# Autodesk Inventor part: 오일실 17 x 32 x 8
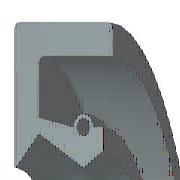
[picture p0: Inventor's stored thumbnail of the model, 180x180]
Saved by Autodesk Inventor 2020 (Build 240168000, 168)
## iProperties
IsCustomPart: 1
Created: 2012-02
Part Number: 오일실 17 x 32 x 8
Material: 고무
Description: 오일-실
Document SubType Name: Modeling
Standard: KS B 2804
Designer: mduedu
Standards Organization: KS
Language: ko-KR
Size Designation: D - 17 32 8
Categories: <MemberInstance><Categories><Category DisplayName="샤프트 부품" InternalName="7f7aeb1f-a693-4053-b835-cee3144e0d98" Mnemonic="SHFT"><Category DisplayName="실링" Intern
Density: 0.93 g/cm^3
Mass: 2.28027 g
Surface Area: 32.1224 cm^2
Volume: 2.45191 cm^3
Appearance: 고무 - 검은색 - 버전 1.1
Author: mduedu
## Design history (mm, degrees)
revolve "본체" stored, may be unused: angle "d17" = 90 deg
revolve "스프링1" stored, may be unused: angle "d18" = 90 deg
body "Solid1"
sketch "스케치1"
  geometry: L1 (0, 16)-(8, 16); L2 (8, 14.25)-(1.75, 14.25); L3 (1.75, 10.25)-(4.9, 8.5); L4 (4.9, 8.5)-(0, 8.5); L5 (0, 0)-(9.586, 0) reference; L6 (4.9, 8.5)-(6.3, 9.375); L7 (0, 18)-(0, -3) reference; L8 (-1.941, 0)-(11.507, 0) reference; L9 (4.2, 10.6)-(1.75, 11.21); L10 (1.75, 11.21)-(1.75, 14.25); L11 (0, 16)-(0, 8.588); L12 (4.9, 8.5)-(0, 8.5); L13 (1.75, 10.25)-(0.152, 8.528); L14 (8, 16)-(8, 14.25); L15 (5.6, 10.6)-(6.3, 10.6); L16 (6.3, 10.6)-(6.3, 9.375); C1 r 0.455 at (4.9, 10.6); A1 r 0.7 centre (4.9, 10.6) between (5.6, 10.6) and (4.2, 10.6); A2 r 0.088 centre (0.088, 8.588) between (0, 8.588) and (0.152, 8.528); 1 further point
  constraints: 28 end point, 5 horizontal alignment, 5 point on line, 4 point on circle, 4 vertical alignment, 3 centre point, 3 tangent, 2 collinear, 2 horizontal, 2 perpendicular, 1 coincident, 1 parallel
  dimensions: "d0" = 32 diameter of L1 L5 (= SD2); "d1" = 1.75 distance of L1.end L2.start (= SD); "d2" = 0.91 diameter of C1 (= SPDI); "d3" = 1.4 diameter of A1 (= SPDA); "d4" = 17 diameter of L3.end L5 (= NND); "d5" = 20.5 diameter of L3.start L5 (= TKDM); "d7" = 22.42 diameter of L9.end L5 (= TKDM + 0.24 x SWDT); "d8" = 1.75 distance between parallel lines of L11 L10 (= SD); "d9" = 4.9 distance from line of L11 C1.centre (= SPDST); "d10" = 21.2 diameter of C1.centre L5 (= HLDM); "d11" = 0.0875 radius of A2 (= 0.25 x LAB); "d12" = 6.3 distance between parallel lines of L11 L16 (= SDI); "d13" = 18.75 diameter of L6.end L5 (= ABDM); "d14" = 8 distance from line of L11 L1.end (= SWDT)
fillet "모깎기1" dims "d6" = 0.3 (= RR)
other parameters: "SD2" = 32 [user parameter; used in 1 equation term], "SWDT" = 8 [user parameter; used in 2 equation terms], "RR" = 0.3 [user parameter; used in 1 equation term], "SD" = 1.75 [user parameter; used in 2 equation terms], "NND" = 17 [user parameter; used in 1 equation term], "SPDA" = 1.4 [user parameter; used in 1 equation term], "SPDI" = 0.91 [user parameter; used in 1 equation term], "TKDM" = 20.5 [user parameter; used in 2 equation terms], "HLDM" = 21.2 [user parameter; used in 1 equation term], "ABDM" = 18.75 [user parameter; used in 1 equation term], "SDI" = 6.3 [user parameter; used in 1 equation term], "SPDST" = 4.9 [user parameter; used in 1 equation term], "LAB" = 0.35 [user parameter; used in 1 equation term], "d15" = 0, "d16" = 0, "d19" = 0
